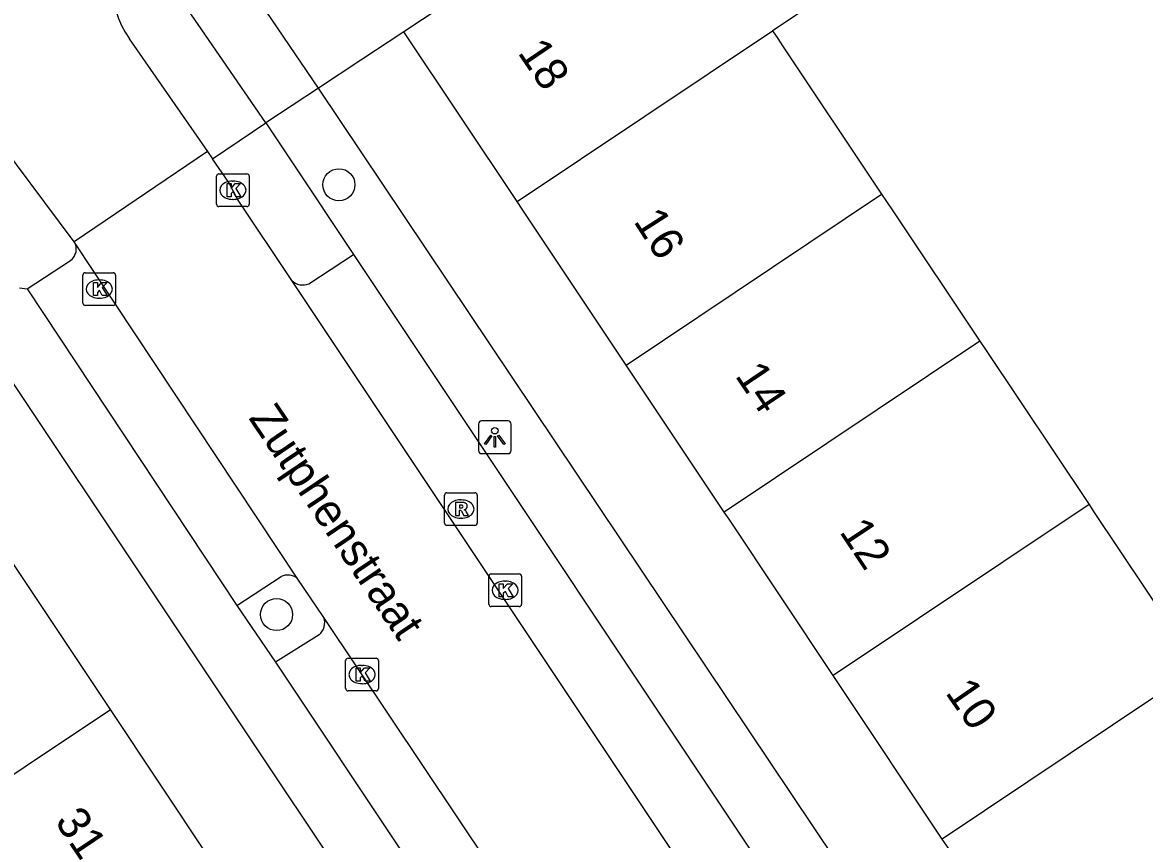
# Model space of a CAD drawing. Extents: x 158352 to 159489, y 383828 to 384597.
# Drawn here: x 158723.41 to 158757.68, y 384309.43 to 384334.39 of the extents above; entities that cross this region are included whole.
import ezdxf

# ---------------------------------------------------------------- set-up
doc = ezdxf.new("R2010")
doc.units = 0
for name, color, linetype in [('IMGEO_Boom', 7, 'Continuous'), ('IMGEO_Groenvoorziening', 7, 'Continuous'), ('IMGEO_Kolk', 7, 'Continuous'), ('IMGEO_Lichtpunt', 7, 'Continuous'), ('IMGEO_Openbare_ruimte_label', 7, 'Continuous'), ('IMGEO_Pand', 7, 'Continuous'), ('IMGEO_Pand_nummerreeks', 7, 'Continuous'), ('IMGEO_Parkeervlak_open', 7, 'Continuous'), ('IMGEO_Rijbaan_lokaal_open', 7, 'Continuous'), ('IMGEO_Rioolput', 7, 'Continuous'), ('IMGEO_Voetpad_gesloten', 7, 'Continuous'), ('IMGEO_Voetpad_open', 7, 'Continuous')]:
    doc.layers.add(name, color=color, linetype=linetype)

msp = doc.modelspace()

# ---------------------------------------------------------------- linework, layer by layer
at = {"layer": 'IMGEO_Boom'}
for centre in [(158733.075, 384329.428), (158731.172, 384316.299)]:
    msp.add_circle(centre, 0.489, dxfattribs=at)
at = {"layer": 'IMGEO_Groenvoorziening'}
msp.add_lwpolyline([(158735.061, 384334.1), (158733.746, 384333.234), (158732.447, 384332.379)], dxfattribs=at)
at = {"layer": 'IMGEO_Kolk'}
for p, q in [((158729.336, 384328.835), (158729.336, 384329.687)), ((158729.411, 384329.761), (158730.263, 384329.761)), ((158730.337, 384329.687), (158730.337, 384328.835)), ((158729.824, 384329.541), (158729.849, 384329.541)), ((158729.847, 384328.981), (158729.822, 384328.981)), ((158730.263, 384328.761), (158729.411, 384328.761)), ((158725.254, 384325.815), (158725.254, 384326.667)), ((158725.329, 384326.741), (158726.181, 384326.741)), ((158726.255, 384326.667), (158726.255, 384325.815)), ((158725.742, 384326.521), (158725.767, 384326.521)), ((158725.765, 384325.961), (158725.74, 384325.961)), ((158726.181, 384325.741), (158725.329, 384325.741)), ((158737.652, 384316.617), (158737.652, 384317.469)), ((158737.727, 384317.543), (158738.579, 384317.543)), ((158738.14, 384317.323), (158738.165, 384317.323)), ((158738.653, 384317.469), (158738.653, 384316.617)), ((158738.163, 384316.763), (158738.138, 384316.763)), ((158738.579, 384316.543), (158737.727, 384316.543)), ((158733.281, 384314.043), (158733.281, 384314.895)), ((158733.356, 384314.969), (158734.208, 384314.969)), ((158734.282, 384314.895), (158734.282, 384314.043)), ((158733.769, 384314.749), (158733.794, 384314.749)), ((158733.792, 384314.189), (158733.767, 384314.189)), ((158734.208, 384313.969), (158733.356, 384313.969))]:
    msp.add_line(p, q, dxfattribs=at)
for points in [[(158729.336, 384328.835), (158729.336, 384329.687)], [(158729.411, 384329.761), (158730.263, 384329.761)], [(158730.337, 384329.687), (158730.337, 384328.835)], [(158729.657, 384329.461), (158729.78, 384329.461), (158729.78, 384329.31), (158729.91, 384329.461), (158730.074, 384329.461), (158729.928, 384329.31), (158730.081, 384329.061), (158729.929, 384329.061), (158729.844, 384329.225), (158729.78, 384329.158), (158729.78, 384329.061), (158729.657, 384329.061), (158729.657, 384329.461)], [(158730.263, 384328.761), (158729.411, 384328.761)], [(158725.254, 384325.815), (158725.254, 384326.667)], [(158725.329, 384326.741), (158726.181, 384326.741)], [(158726.255, 384326.667), (158726.255, 384325.815)], [(158725.575, 384326.441), (158725.698, 384326.441), (158725.698, 384326.29), (158725.828, 384326.441), (158725.992, 384326.441), (158725.846, 384326.29), (158725.999, 384326.041), (158725.847, 384326.041), (158725.762, 384326.205), (158725.698, 384326.138), (158725.698, 384326.041), (158725.575, 384326.041), (158725.575, 384326.441)], [(158726.181, 384325.741), (158725.329, 384325.741)], [(158737.652, 384316.617), (158737.652, 384317.469)], [(158737.727, 384317.543), (158738.579, 384317.543)], [(158738.653, 384317.469), (158738.653, 384316.617)], [(158737.973, 384317.243), (158738.096, 384317.243), (158738.096, 384317.092), (158738.226, 384317.243), (158738.39, 384317.243), (158738.244, 384317.092), (158738.397, 384316.843), (158738.245, 384316.843), (158738.16, 384317.007), (158738.096, 384316.94), (158738.096, 384316.843), (158737.973, 384316.843), (158737.973, 384317.243)], [(158738.579, 384316.543), (158737.727, 384316.543)], [(158733.281, 384314.043), (158733.281, 384314.895)], [(158733.356, 384314.969), (158734.208, 384314.969)], [(158734.282, 384314.895), (158734.282, 384314.043)], [(158733.602, 384314.669), (158733.725, 384314.669), (158733.725, 384314.518), (158733.855, 384314.669), (158734.019, 384314.669), (158733.873, 384314.518), (158734.026, 384314.269), (158733.874, 384314.269), (158733.789, 384314.433), (158733.725, 384314.366), (158733.725, 384314.269), (158733.602, 384314.269), (158733.602, 384314.669)], [(158734.208, 384313.969), (158733.356, 384313.969)]]:
    msp.add_lwpolyline(points, dxfattribs=at)
for centre, start, end in [((158729.413, 384329.685), 91.552, 178.448), ((158729.413, 384329.685), 91.552, 178.448), ((158730.261, 384329.685), 1.552, 88.448), ((158730.261, 384329.685), 1.552, 88.448), ((158729.413, 384328.837), 181.552, 268.448), ((158729.413, 384328.837), 181.552, 268.448), ((158730.261, 384328.837), 271.552, 358.448), ((158730.261, 384328.837), 271.552, 358.448), ((158725.331, 384326.665), 91.552, 178.448), ((158725.331, 384326.665), 91.552, 178.448), ((158726.179, 384326.665), 1.552, 88.448), ((158726.179, 384326.665), 1.552, 88.448), ((158725.331, 384325.817), 181.552, 268.448), ((158725.331, 384325.817), 181.552, 268.448), ((158726.179, 384325.817), 271.552, 358.448), ((158726.179, 384325.817), 271.552, 358.448), ((158737.729, 384317.467), 91.552, 178.448), ((158737.729, 384317.467), 91.552, 178.448), ((158738.577, 384317.467), 1.552, 88.448), ((158738.577, 384317.467), 1.552, 88.448), ((158737.729, 384316.619), 181.552, 268.448), ((158737.729, 384316.619), 181.552, 268.448), ((158738.577, 384316.619), 271.552, 358.448), ((158738.577, 384316.619), 271.552, 358.448), ((158733.358, 384314.893), 91.552, 178.448), ((158733.358, 384314.893), 91.552, 178.448), ((158734.206, 384314.893), 1.552, 88.448), ((158734.206, 384314.893), 1.552, 88.448), ((158733.358, 384314.045), 181.552, 268.448), ((158733.358, 384314.045), 181.552, 268.448), ((158734.206, 384314.045), 271.552, 358.448), ((158734.206, 384314.045), 271.552, 358.448)]:
    msp.add_arc(centre, 0.0765, start, end, dxfattribs=at)
for centre, major_axis, ratio, start_param, end_param in [((158729.823, 384329.261), (-0.387, 0.002), 0.722429, 4.712389, 7.853982), ((158729.848, 384329.261), (-0.39, 0.002), 0.717154, 1.570796, 4.712389), ((158725.741, 384326.241), (-0.387, 0.002), 0.722429, 4.712389, 7.853982), ((158725.766, 384326.241), (-0.39, 0.002), 0.717154, 1.570796, 4.712389), ((158738.139, 384317.043), (-0.387, 0.002), 0.722429, 4.712389, 7.853982), ((158738.164, 384317.043), (-0.39, 0.002), 0.717154, 1.570796, 4.712389), ((158733.768, 384314.469), (-0.387, 0.002), 0.722429, 4.712389, 7.853982), ((158733.793, 384314.469), (-0.39, 0.002), 0.717154, 1.570796, 4.712389)]:
    msp.add_ellipse(centre, major_axis=major_axis, ratio=ratio, start_param=start_param, end_param=end_param, dxfattribs=at)
at = {"layer": 'IMGEO_Lichtpunt'}
for p, q in [((158737.337, 384322.118), (158737.337, 384321.311)), ((158737.337, 384322.118), (158737.337, 384321.311)), ((158738.239, 384322.213), (158737.431, 384322.213)), ((158738.239, 384322.213), (158737.431, 384322.213)), ((158738.333, 384321.311), (158738.333, 384322.118)), ((158738.333, 384321.311), (158738.333, 384322.118)), ((158737.431, 384321.217), (158738.239, 384321.217)), ((158737.431, 384321.217), (158738.239, 384321.217))]:
    msp.add_line(p, q, dxfattribs=at)
for points in [[(158737.711, 384321.782), (158737.75, 384321.754), (158737.562, 384321.492), (158737.524, 384321.519), (158737.711, 384321.782)], [(158737.813, 384321.734), (158737.86, 384321.734), (158737.86, 384321.412), (158737.813, 384321.412), (158737.813, 384321.734)], [(158737.923, 384321.754), (158737.961, 384321.781), (158738.148, 384321.519), (158738.109, 384321.491), (158737.923, 384321.754)]]:
    msp.add_lwpolyline(points, dxfattribs=at)
msp.add_circle((158737.836, 384321.916), 0.0994, dxfattribs=at)
for centre, start, end in [((158737.431, 384322.118), 90, 180), ((158737.431, 384322.118), 90, 180), ((158738.239, 384322.118), 0, 90), ((158738.239, 384322.118), 0, 90), ((158737.431, 384321.311), 180, 270), ((158737.431, 384321.311), 180, 270), ((158738.239, 384321.311), 270, 0), ((158738.239, 384321.311), 270, 360)]:
    msp.add_arc(centre, 0.0946, start, end, dxfattribs=at)
at = {"layer": 'IMGEO_Pand'}
for points in [[(158744.975, 384340.685), (158748.402, 384335.525), (158746.317, 384334.13)], [(158738.413, 384336.326), (158735.061, 384334.1)], [(158738.519, 384328.914), (158735.061, 384334.1)], [(158738.519, 384328.914), (158746.317, 384334.13)], [(158746.317, 384334.13), (158746.477, 384333.891), (158746.627, 384333.666), (158749.65, 384329.141)], [(158741.847, 384323.922), (158749.65, 384329.141)], [(158749.65, 384329.141), (158749.797, 384328.921), (158749.988, 384328.636), (158752.651, 384324.65)], [(158741.847, 384323.922), (158738.671, 384328.686), (158738.519, 384328.914)], [(158752.651, 384324.65), (158744.843, 384319.429)], [(158752.651, 384324.65), (158752.799, 384324.429), (158755.986, 384319.66)], [(158744.843, 384319.429), (158741.992, 384323.705), (158741.847, 384323.922)], [(158748.172, 384314.437), (158744.989, 384319.21), (158744.843, 384319.429)], [(158755.986, 384319.66), (158748.172, 384314.437)], [(158755.986, 384319.66), (158756.125, 384319.452), (158759.321, 384314.671)], [(158726.098, 384313.399), (158722.779, 384318.379)], [(158759.321, 384314.671), (158751.501, 384309.445)], [(158751.501, 384309.445), (158748.31, 384314.23), (158748.172, 384314.437)], [(158718.236, 384308.158), (158726.098, 384313.399)], [(158729.096, 384308.902), (158726.098, 384313.399)], [(158754.497, 384304.952), (158751.64, 384309.236), (158751.501, 384309.445)]]:
    msp.add_lwpolyline(points, dxfattribs=at)
at = {"layer": 'IMGEO_Parkeervlak_open'}
for points in [[(158723.554, 384326.244), (158724.879, 384327.115)], [(158729.962, 384316.577), (158731.314, 384317.466)], [(158732.47, 384315.682), (158731.136, 384314.846)]]:
    msp.add_lwpolyline(points, dxfattribs=at)
for centre, radius, start, end in [((158724.628, 384327.459), 0.426, 306.1442, 32.0102), ((158731.509, 384316.994), 0.511, 55.7299, 112.4497), ((158732.153, 384316.056), 0.49, 310.2636, 18.1618)]:
    msp.add_arc(centre, radius, start, end, dxfattribs=at)
at = {"layer": 'IMGEO_Rijbaan_lokaal_open'}
for points in [[(158726.674, 384333.888), (158726.901, 384333.551), (158729.058, 384330.442)], [(158724.989, 384327.685), (158722.32, 384331.246)], [(158729.058, 384330.442), (158724.989, 384327.685)], [(158729.058, 384330.442), (158729.213, 384330.219)], [(158731.636, 384326.508), (158729.981, 384328.983), (158729.716, 384329.495), (158729.213, 384330.219)], [(158731.797, 384317.416), (158724.989, 384327.685)], [(158745.626, 384305.518), (158731.636, 384326.508)], [(158732.619, 384316.209), (158731.797, 384317.416)], [(158748.867, 384291.915), (158732.619, 384316.209)]]:
    msp.add_lwpolyline(points, dxfattribs=at)
msp.add_arc((158729.114, 384335.585), 2.972, 143.9473, 214.8223, dxfattribs=at)
at = {"layer": 'IMGEO_Rioolput'}
for p, q in [((158736.375, 384320.022), (158737.227, 384320.022)), ((158736.3, 384319.096), (158736.3, 384319.948)), ((158736.788, 384319.802), (158736.813, 384319.802)), ((158737.301, 384319.948), (158737.301, 384319.096)), ((158737.227, 384319.022), (158736.375, 384319.022)), ((158736.811, 384319.242), (158736.786, 384319.242))]:
    msp.add_line(p, q, dxfattribs=at)
for points in [[(158736.375, 384320.022), (158737.227, 384320.022)], [(158736.3, 384319.096), (158736.3, 384319.948)], [(158736.889, 384319.72), (158736.637, 384319.722), (158736.637, 384319.322)], [(158737.301, 384319.948), (158737.301, 384319.096)], [(158736.637, 384319.322), (158736.761, 384319.322), (158736.761, 384319.484), (158736.772, 384319.484)], [(158736.815, 384319.641), (158736.761, 384319.641), (158736.761, 384319.56)], [(158736.761, 384319.56), (158736.813, 384319.56)], [(158736.819, 384319.455), (158736.89, 384319.322), (158737.03, 384319.322), (158736.965, 384319.448)], [(158737.227, 384319.022), (158736.375, 384319.022)]]:
    msp.add_lwpolyline(points, dxfattribs=at)
for centre, radius, start, end in [((158736.377, 384319.946), 0.0765, 91.552, 178.448), ((158736.377, 384319.946), 0.0765, 91.552, 178.448), ((158737.225, 384319.946), 0.0765, 1.552, 88.448), ((158737.225, 384319.946), 0.0765, 1.552, 88.448), ((158736.888, 384319.61), 0.109, 350.3612, 89.416), ((158736.771, 384319.431), 0.0533, 26.0293, 88.6989), ((158736.797, 384319.749), 0.19, 274.7715, 282.9687), ((158736.821, 384319.545), 0.0964, 77.0061, 93.1865), ((158736.835, 384319.602), 0.0378, 276.6634, 79.6772), ((158736.886, 384319.61), 0.112, 277.5842, 350.9817), ((158736.87, 384319.395), 0.108, 29.5134, 73.7905), ((158736.377, 384319.098), 0.0765, 181.552, 268.448), ((158736.377, 384319.098), 0.0765, 181.552, 268.448), ((158737.225, 384319.098), 0.0765, 271.552, 358.448), ((158737.225, 384319.098), 0.0765, 271.552, 358.448)]:
    msp.add_arc(centre, radius, start, end, dxfattribs=at)
for centre, major_axis, ratio, start_param, end_param in [((158736.787, 384319.522), (-0.387, 0.002), 0.722429, 4.712389, 7.853982), ((158736.812, 384319.522), (-0.39, 0.002), 0.717154, 1.570796, 4.712389)]:
    msp.add_ellipse(centre, major_axis=major_axis, ratio=ratio, start_param=start_param, end_param=end_param, dxfattribs=at)
at = {"layer": 'IMGEO_Voetpad_gesloten'}
for points in [[(158732.447, 384332.379), (158728.888, 384337.629)], [(158730.838, 384331.32), (158726.711, 384337.334)], [(158732.447, 384332.379), (158730.838, 384331.32)]]:
    msp.add_lwpolyline(points, dxfattribs=at)
at = {"layer": 'IMGEO_Voetpad_open'}
for points in [[(158759.994, 384293.99), (158758.742, 384293.153), (158732.447, 384332.379)], [(158729.213, 384330.219), (158730.838, 384331.32)], [(158730.838, 384331.32), (158731.653, 384330.097), (158733.516, 384327.301)], [(158732.156, 384326.406), (158733.516, 384327.301)], [(158733.516, 384327.301), (158747.086, 384306.935)], [(158723.317, 384326.283), (158723.554, 384326.244)], [(158723.554, 384326.244), (158729.962, 384316.577)], [(158721.854, 384325.255), (158761.364, 384266.025), (158758.812, 384264.322)], [(158729.962, 384316.577), (158731.136, 384314.846)], [(158731.136, 384314.846), (158746.983, 384291.062)]]:
    msp.add_lwpolyline(points, dxfattribs=at)
msp.add_arc((158731.969, 384326.828), 0.462, 223.8996, 293.9047, dxfattribs=at)

# ---------------------------------------------------------------- texts
at = {"layer": 'IMGEO_Openbare_ruimte_label'}
msp.add_text('Zutphenstraat', height=1, rotation=303.992, dxfattribs=at).set_placement((158730.299, 384322.3))
at = {"layer": 'IMGEO_Pand_nummerreeks'}
for s, rotation, p in [('18', 304.1423, (158738.515, 384333.463)), ('16', 302.7214, (158742.054, 384328.312)), ('14', 303.959, (158745.154, 384323.595)), ('12', 303.6725, (158748.34, 384318.828)), ('10', 304.6981, (158751.574, 384313.914)), ('31', 303.8316, (158724.379, 384309.979))]:
    msp.add_text(s, height=1, rotation=rotation, dxfattribs=at).set_placement(p)

doc.saveas('drawing.dxf')
